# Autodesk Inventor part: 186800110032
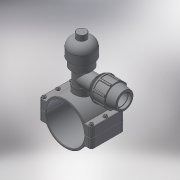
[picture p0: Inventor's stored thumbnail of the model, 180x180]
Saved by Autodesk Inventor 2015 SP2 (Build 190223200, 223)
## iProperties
Created: 2017-05
Part Number: 186800110032
Material: Generic
Description: PLASSON MECHANICAL TAPPING VALVE 110-32
Document SubType Name: Modeling
Designer: KIM
Density: 1 g/cm^3
Appearance: Default
Author: KIM
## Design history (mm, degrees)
derived "18680.ipt"
feature "Solid1::18680.ipt"
feature "Solid2::18680.ipt"
tag "TaggingFeature1"
body "Solid1"
other parameters: "d0" = 121, "d1" = 165, "d2" = 55, "d4" = 116, "d5" = 0, "d6" = 8.25, "d7" = 165, "d8" = 0.1, "d10" = 0, "d11" = 1.1, "d14" = 50.6376, "d20" = 1.1, "d23" = 1.1, "d36" = 13, "d37" = 10.4, "d38" = 63, "d39" = 0, "d40" = 3, "d41" = 5, "d42" = 0, "d43" = 8, "d44" = 3, "d45" = 0, "d46" = 1.1, "d51" = 91, "d52" = 38.952, "d53" = 25, "d54" = 0, "d55" = 32, "d57" = 0, "d58" = 118.8, "d60" = 0, "d62" = 13, "d63" = 10.4, "d66" = 95.2, "d67" = 32, "d68" = 11.25, "d69" = 27, "d70" = 64, "d71" = 48, "d72" = 1.92857, "d73" = 51.2, "d74" = 120 deg, "d75" = 48, "d76" = 10 deg, "d77" = 57.6, "d78" = 40.5, "d79" = 67, "d80" = 25.6, "d81" = 135, "d82" = 6.7, "d87" = 19.28571, "d90" = 59.52, "d91" = 35 deg, "d92" = 17.5 deg, "d94" = 0, "d96" = 360 deg, "d98" = 0.64, "d99" = 73.7, "d100" = 38.4, "d101" = 135 deg, "d102" = 1.28, "d105" = 3.2, "d106" = 0, "d107" = 0.1, "d109" = 50.6376, "d112" = 34.85714, "d113" = 4.5, "d116" = 0, "d121" = 46.7424, "d122" = 77.904, "d123" = 66.2184, "d124" = 45 deg, "d125" = 219.6, "d126" = 244, "d127" = 146.4, "d128" = 1, "B_" = 32, "G_" = 38.952, "A_" = 91, "L_" = 165, "L_1" = 116, "l_2" = 25, "d_1" = 32, "E_" = 64, "l_" = 67, "H_" = 135, "H_2" = 244
